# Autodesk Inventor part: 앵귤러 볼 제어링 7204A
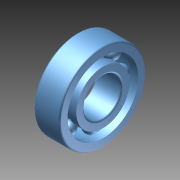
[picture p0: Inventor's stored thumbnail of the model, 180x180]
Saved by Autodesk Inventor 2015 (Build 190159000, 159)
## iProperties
Created: 2024-12
Part Number: 앵귤러 볼 제어링 7204A
Material: 일반
Document SubType Name: Modeling
Designer: 10401
Density: 1 g/cm^3
Appearance: 기본값
Author: 10401
Author: jhkim
Description: 앵귤러 콘택트 볼 베어링
Creation Date: 2024-11-28
Sending System: Autodesk Inventor 2025
Preprocessor: ST-DEVELOPER v20
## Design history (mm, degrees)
node "앵귤러 볼 제어링 7204A1"
body "Solid1"
node "Solid1_1"
node "Solid1_2"
node "Solid1_3"
node "Solid1_4"
node "Solid1_5"
node "Solid1_6"
node "Solid1_7"
node "Solid1_8"
node "Solid1_9"
node "기준1"
node "기준2"
node "기준3"
node "기준4"
node "기준5"
node "기준6"
node "기준7"
node "기준8"
node "기준9"
node "기준10"
